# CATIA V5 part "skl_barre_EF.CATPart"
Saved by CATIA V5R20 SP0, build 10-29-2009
Part number: skl_barre_EF
Publications: "Axe_pivot_EF_F", "Axe_pivot_EF_E", "Droite_EF"
Bounding box of the stored display mesh (mm): x -5 to 0, y -6 to 106, z -5.997 to 55.997
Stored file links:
  D:\Dropbox\IAO_2012\IAO_2012_742_prousseau\skl_barre_EF.CATPart
  D:\Dropbox\IAO_2012\IAO_2012_742_prousseau\skl_IAO.CATProduct
  D:\Dropbox\IAO_2012\IAO_2012_742_prousseau\skl_barre_AB.CATPart
  D:\Dropbox\IAO_2012\IAO_2012_742_prousseau\skl_barre_DE.CATPart
  D:\Dropbox\IAO_2012\IAO_2012_742_prousseau\skl_barre_BC.CATPart
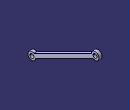
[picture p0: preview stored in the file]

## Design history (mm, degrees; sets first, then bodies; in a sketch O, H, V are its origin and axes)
Set1
  Line1 "Droite_FA": linked copy from another document
  Point1 "Point_A": linked copy from another document
  Point2 "Point_E": linked copy from another document
Set2
  Line2 "Droite_EF": type PtPt, FirstPoint Point3, SecondPoint Point4
  Point3 "Point_E": stored without definition
  Point4 "Point_F": stored without definition
  Line3 "Axe_pivot_EF_E": type Normal, RefPoint Point3, RefSkin Plane1, Start -20, End 20
  Plane1 "Plan_Ref": stored without definition
  Line4 "Axe_pivot_EF_F": type Normal, RefPoint Point4, RefSkin Plane2, Start -20, End 20
  Plane2 "Plan_Ref": stored without definition
Body1 (main body)
  Sketch1 on Plane2, origin (0, 0, 0), H (0, 1, 0), V (0, 0, 1)
    line L1 (3.3059, 5.0071) -> (94.0108, 50.3595)
    line L2 (96.6941, 44.9929) -> (5.9892, -0.3595)
    reference projected line E1 (100, 50) -> (0, 0) from Line2
    reference projected line E2 (100, 50) -> (0, 0) from Line2
    reference projected line E3 (100, 50) -> (0, 0) from Line2
    arc A1 centre (100, 50) radius 6 from (96.6941, 44.9929) to (94.0108, 50.3595) ccw
    point P1 (100, 50)
    circle A2 centre (100, 50) radius 3
    circle A3 centre (0, 0) radius 3
    point P2 (0, 0)
    arc A4 centre (0, 0) radius 6 from (3.3059, 5.0071) to (5.9892, -0.3595) ccw
    reference projected point E4 (100, 50) from Point2
    distance L1 E3 = 3
    radius A2 = 3
    radius A1 = 6
    radius A3 = 3
    radius A4 = 6
    parallelism: L1 L2, L2 E1
    symmetry: L2 L1 E2
    coincidence: P2 O, P1 E4
  Pad1: profile Sketch1, direction (-1, 0, 0), length 5
  Sketch2, origin (0, 0, 0), H (0, 1, 0), V (0, 0, 1)
    line L1 (-52.1837, 194.702) -> (19.0037, 150.21)
    line L2 (22.1837, 155.298) -> (-49.0037, 199.79)
    reference projected line E1 (-55, 200) -> (25, 150)
    reference projected line E2 (-55, 200) -> (25, 150)
    reference projected line E3 (-55, 200) -> (25, 150)
    arc A1 centre (25, 150) radius 6 from (19.0037, 150.21) to (22.1837, 155.298) ccw
    point P1 (25, 150)
    reference projected point E4 (25, 150)
    circle A2 centre (25, 150) radius 3
    point P2 (25, 150)
    reference projected point E5 (25, 150)
    circle A3 centre (-55, 200) radius 3
    point P5 (-55, 200)
    reference projected point E6 (-55, 200)
    arc A4 centre (-55, 200) radius 6 from (-49.0037, 199.79) to (-52.1837, 194.702) ccw
    point P6 (-55, 200)
    reference projected point E7 (-55, 200)
    distance L2 E3 = 3
    radius A2 = 3
    radius A1 = 6
    radius A3 = 3
    radius A4 = 6
    parallelism: L1 L2, L1 E1
    symmetry: L1 L2 E2
    coincidence: P1 E4, P2 E5, P5 E6, E7 P6
  Pad2: profile Sketch2, direction (1, 0, 0), length 5, deactivated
